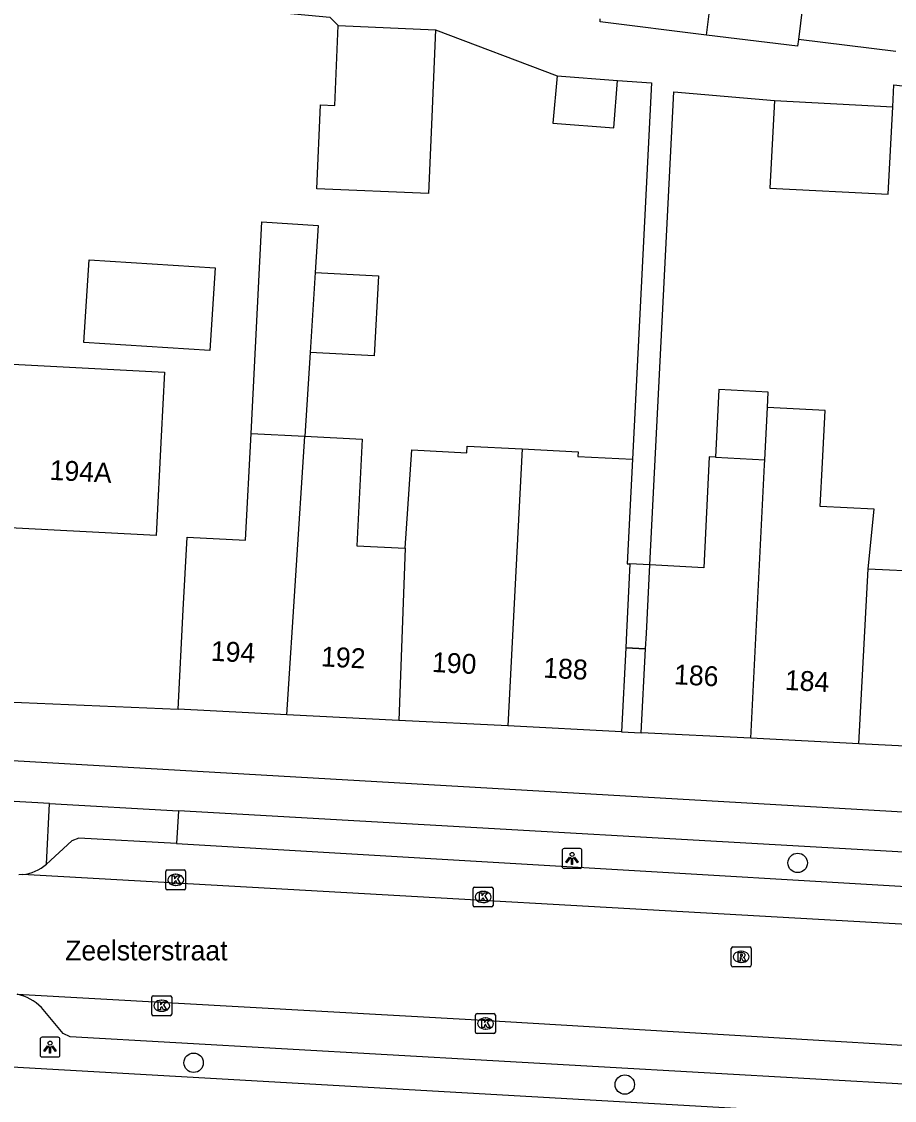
# Model space of a CAD drawing. Extents: x 158087 to 159494, y 382905 to 383981.
# Drawn here: x 158409.1 to 158453.1, y 383167.5 to 383221.8 of the extents above; entities that cross this region are included whole.
import ezdxf

# ---------------------------------------------------------------- set-up
doc = ezdxf.new("R2010")
doc.units = 0
for name, color, linetype in [('IMGEO_Boom', 7, 'Continuous'), ('IMGEO_Fietspad_gesloten', 7, 'Continuous'), ('IMGEO_Kolk', 7, 'Continuous'), ('IMGEO_Lichtpunt', 7, 'Continuous'), ('IMGEO_Openbare_ruimte_label', 7, 'Continuous'), ('IMGEO_Pand', 7, 'Continuous'), ('IMGEO_Pand_nummerreeks', 7, 'Continuous'), ('IMGEO_Pand_overbouw', 7, 'Continuous'), ('IMGEO_Parkeervlak_open', 7, 'Continuous'), ('IMGEO_Rijbaan_lokaal_gesloten', 7, 'Continuous'), ('IMGEO_Rioolput', 7, 'Continuous'), ('IMGEO_Voetpad_open', 7, 'Continuous')]:
    doc.layers.add(name, color=color, linetype=linetype)

msp = doc.modelspace()

# ---------------------------------------------------------------- linework, layer by layer
at = {"layer": 'IMGEO_Boom'}
for centre in [(158448.215, 383179.424), (158417.805, 383169.369), (158439.511, 383168.271)]:
    msp.add_circle(centre, 0.489, dxfattribs=at)
at = {"layer": 'IMGEO_Fietspad_gesloten'}
for points in [[(158375.483, 383186.486), (158469.526, 383181.066)], [(158410.542, 383182.413), (158376.349, 383184.334)], [(158410.542, 383182.413), (158417.046, 383182.047)], [(158474.658, 383178.653), (158459.444, 383179.637), (158417.046, 383182.047)], [(158375.415, 383171.065), (158464.529, 383165.969), (158487.406, 383164.364)]]:
    msp.add_lwpolyline(points, dxfattribs=at)
at = {"layer": 'IMGEO_Kolk'}
for p, q in [((158416.402, 383178.144), (158416.402, 383178.996)), ((158416.477, 383179.07), (158417.329, 383179.07)), ((158416.89, 383178.85), (158416.915, 383178.85)), ((158417.403, 383178.996), (158417.403, 383178.144)), ((158417.329, 383178.07), (158416.477, 383178.07)), ((158416.913, 383178.29), (158416.888, 383178.29)), ((158431.878, 383177.284), (158431.878, 383178.136)), ((158431.953, 383178.21), (158432.805, 383178.21)), ((158432.879, 383178.136), (158432.879, 383177.284)), ((158432.366, 383177.99), (158432.391, 383177.99)), ((158432.805, 383177.21), (158431.953, 383177.21)), ((158432.389, 383177.43), (158432.364, 383177.43)), ((158415.699, 383171.809), (158415.699, 383172.661)), ((158415.774, 383172.735), (158416.626, 383172.735)), ((158416.7, 383172.661), (158416.7, 383171.809)), ((158416.187, 383172.515), (158416.212, 383172.515)), ((158416.626, 383171.735), (158415.774, 383171.735)), ((158416.21, 383171.955), (158416.185, 383171.955)), ((158431.997, 383170.915), (158431.997, 383171.767)), ((158432.072, 383171.841), (158432.924, 383171.841)), ((158432.485, 383171.621), (158432.51, 383171.621)), ((158432.998, 383171.767), (158432.998, 383170.915)), ((158432.508, 383171.061), (158432.483, 383171.061)), ((158432.924, 383170.841), (158432.072, 383170.841))]:
    msp.add_line(p, q, dxfattribs=at)
for points in [[(158416.402, 383178.144), (158416.402, 383178.996)], [(158416.477, 383179.07), (158417.329, 383179.07)], [(158416.723, 383178.77), (158416.846, 383178.77), (158416.846, 383178.619), (158416.976, 383178.77), (158417.14, 383178.77), (158416.994, 383178.619), (158417.147, 383178.37), (158416.995, 383178.37), (158416.91, 383178.534), (158416.846, 383178.467), (158416.846, 383178.37), (158416.723, 383178.37), (158416.723, 383178.77)], [(158417.403, 383178.996), (158417.403, 383178.144)], [(158417.329, 383178.07), (158416.477, 383178.07)], [(158431.878, 383177.284), (158431.878, 383178.136)], [(158431.953, 383178.21), (158432.805, 383178.21)], [(158432.879, 383178.136), (158432.879, 383177.284)], [(158432.199, 383177.91), (158432.322, 383177.91), (158432.322, 383177.759), (158432.452, 383177.91), (158432.616, 383177.91), (158432.47, 383177.759), (158432.623, 383177.51), (158432.471, 383177.51), (158432.386, 383177.674), (158432.322, 383177.607), (158432.322, 383177.51), (158432.199, 383177.51), (158432.199, 383177.91)], [(158432.805, 383177.21), (158431.953, 383177.21)], [(158415.699, 383171.809), (158415.699, 383172.661)], [(158415.774, 383172.735), (158416.626, 383172.735)], [(158416.7, 383172.661), (158416.7, 383171.809)], [(158416.02, 383172.435), (158416.143, 383172.435), (158416.143, 383172.284), (158416.273, 383172.435), (158416.437, 383172.435), (158416.291, 383172.284), (158416.444, 383172.035), (158416.292, 383172.035), (158416.207, 383172.199), (158416.143, 383172.132), (158416.143, 383172.035), (158416.02, 383172.035), (158416.02, 383172.435)], [(158416.626, 383171.735), (158415.774, 383171.735)], [(158431.997, 383170.915), (158431.997, 383171.767)], [(158432.072, 383171.841), (158432.924, 383171.841)], [(158432.318, 383171.541), (158432.441, 383171.541), (158432.441, 383171.39), (158432.571, 383171.541), (158432.735, 383171.541), (158432.589, 383171.39), (158432.742, 383171.141), (158432.59, 383171.141), (158432.505, 383171.305), (158432.441, 383171.238), (158432.441, 383171.141), (158432.318, 383171.141), (158432.318, 383171.541)], [(158432.998, 383171.767), (158432.998, 383170.915)], [(158432.924, 383170.841), (158432.072, 383170.841)]]:
    msp.add_lwpolyline(points, dxfattribs=at)
for centre, start, end in [((158416.479, 383178.994), 91.552, 178.448), ((158416.479, 383178.994), 91.552, 178.448), ((158417.327, 383178.994), 1.552, 88.448), ((158417.327, 383178.994), 1.552, 88.448), ((158416.479, 383178.146), 181.552, 268.448), ((158416.479, 383178.146), 181.552, 268.448), ((158417.327, 383178.146), 271.552, 358.448), ((158417.327, 383178.146), 271.552, 358.448), ((158431.955, 383178.134), 91.552, 178.448), ((158431.955, 383178.134), 91.552, 178.448), ((158432.803, 383178.134), 1.552, 88.448), ((158432.803, 383178.134), 1.552, 88.448), ((158431.955, 383177.286), 181.552, 268.448), ((158431.955, 383177.286), 181.552, 268.448), ((158432.803, 383177.286), 271.552, 358.448), ((158432.803, 383177.286), 271.552, 358.448), ((158415.776, 383172.659), 91.552, 178.448), ((158415.776, 383172.659), 91.552, 178.448), ((158416.624, 383172.659), 1.552, 88.448), ((158416.624, 383172.659), 1.552, 88.448), ((158415.776, 383171.811), 181.552, 268.448), ((158415.776, 383171.811), 181.552, 268.448), ((158416.624, 383171.811), 271.552, 358.448), ((158416.624, 383171.811), 271.552, 358.448), ((158432.074, 383171.765), 91.552, 178.448), ((158432.074, 383171.765), 91.552, 178.448), ((158432.922, 383171.765), 1.552, 88.448), ((158432.922, 383171.765), 1.552, 88.448), ((158432.074, 383170.917), 181.552, 268.448), ((158432.074, 383170.917), 181.552, 268.448), ((158432.922, 383170.917), 271.552, 358.448), ((158432.922, 383170.917), 271.552, 358.448)]:
    msp.add_arc(centre, 0.0765, start, end, dxfattribs=at)
for centre, major_axis, ratio, start_param, end_param in [((158416.889, 383178.57), (-0.387, 0.002), 0.722429, 4.712389, 7.853982), ((158416.914, 383178.57), (-0.39, 0.002), 0.717154, 1.570796, 4.712389), ((158432.365, 383177.71), (-0.387, 0.002), 0.722429, 4.712389, 7.853982), ((158432.39, 383177.71), (-0.39, 0.002), 0.717154, 1.570796, 4.712389), ((158416.186, 383172.235), (-0.387, 0.002), 0.722429, 4.712389, 7.853982), ((158416.211, 383172.235), (-0.39, 0.002), 0.717154, 1.570796, 4.712389), ((158432.484, 383171.341), (-0.387, 0.002), 0.722429, 4.712389, 7.853982), ((158432.509, 383171.341), (-0.39, 0.002), 0.717154, 1.570796, 4.712389)]:
    msp.add_ellipse(centre, major_axis=major_axis, ratio=ratio, start_param=start_param, end_param=end_param, dxfattribs=at)
at = {"layer": 'IMGEO_Lichtpunt'}
for p, q in [((158436.36, 383180.052), (158436.36, 383179.245)), ((158436.36, 383180.052), (158436.36, 383179.245)), ((158437.262, 383180.147), (158436.454, 383180.147)), ((158437.262, 383180.147), (158436.454, 383180.147)), ((158437.356, 383179.245), (158437.356, 383180.052)), ((158437.356, 383179.245), (158437.356, 383180.052)), ((158436.454, 383179.151), (158437.262, 383179.151)), ((158436.454, 383179.151), (158437.262, 383179.151)), ((158410.081, 383170.559), (158410.081, 383169.752)), ((158410.081, 383170.559), (158410.081, 383169.752)), ((158410.983, 383170.654), (158410.175, 383170.654)), ((158410.983, 383170.654), (158410.175, 383170.654)), ((158411.077, 383169.752), (158411.077, 383170.559)), ((158411.077, 383169.752), (158411.077, 383170.559)), ((158410.175, 383169.658), (158410.983, 383169.658)), ((158410.175, 383169.658), (158410.983, 383169.658))]:
    msp.add_line(p, q, dxfattribs=at)
for points in [[(158436.734, 383179.716), (158436.773, 383179.688), (158436.585, 383179.426), (158436.547, 383179.453), (158436.734, 383179.716)], [(158436.836, 383179.668), (158436.883, 383179.668), (158436.883, 383179.346), (158436.836, 383179.346), (158436.836, 383179.668)], [(158436.946, 383179.688), (158436.984, 383179.715), (158437.171, 383179.453), (158437.132, 383179.425), (158436.946, 383179.688)], [(158410.455, 383170.223), (158410.494, 383170.195), (158410.306, 383169.933), (158410.268, 383169.96), (158410.455, 383170.223)], [(158410.557, 383170.175), (158410.604, 383170.175), (158410.604, 383169.853), (158410.557, 383169.853), (158410.557, 383170.175)], [(158410.667, 383170.195), (158410.705, 383170.222), (158410.892, 383169.96), (158410.853, 383169.932), (158410.667, 383170.195)]]:
    msp.add_lwpolyline(points, dxfattribs=at)
for centre in [(158436.859, 383179.85), (158410.58, 383170.357)]:
    msp.add_circle(centre, 0.0994, dxfattribs=at)
for centre, start, end in [((158436.454, 383180.052), 90, 180), ((158436.454, 383180.052), 90, 180), ((158437.262, 383180.052), 0, 90), ((158437.262, 383180.052), 0, 90), ((158436.454, 383179.245), 180, 270), ((158436.454, 383179.245), 180, 270), ((158437.262, 383179.245), 270, 0), ((158437.262, 383179.245), 270, 360), ((158410.175, 383170.559), 90, 180), ((158410.175, 383170.559), 90, 180), ((158410.983, 383170.559), 0, 90), ((158410.983, 383170.559), 0, 90), ((158410.175, 383169.752), 180, 270), ((158410.175, 383169.752), 180, 270), ((158410.983, 383169.752), 270, 0), ((158410.983, 383169.752), 270, 360)]:
    msp.add_arc(centre, 0.0946, start, end, dxfattribs=at)
at = {"layer": 'IMGEO_Pand'}
for points in [[(158443.627, 383221.079), (158444.058, 383224.585), (158448.643, 383224.022)], [(158448.643, 383224.022), (158448.254, 383220.849)], [(158429.982, 383221.345), (158429.796, 383216.965), (158429.631, 383213.107), (158424.008, 383213.346), (158424.188, 383217.574), (158424.911, 383217.543), (158425.082, 383221.554)], [(158425.082, 383221.554), (158429.982, 383221.345)], [(158448.254, 383220.849), (158448.213, 383220.516), (158443.627, 383221.079)], [(158453.163, 383220.247), (158448.254, 383220.849)], [(158436.103, 383219.029), (158435.887, 383216.645), (158438.967, 383216.412), (158439.147, 383218.799)], [(158436.103, 383219.029), (158439.147, 383218.799)], [(158447.044, 383217.782), (158446.812, 383213.381), (158452.775, 383213.066), (158453.008, 383217.467)], [(158447.044, 383217.782), (158453.008, 383217.467)], [(158420.694, 383201.031), (158421.236, 383211.685), (158424.075, 383211.503), (158423.923, 383209.131)], [(158418.622, 383205.199), (158412.275, 383205.605), (158412.541, 383209.772), (158418.888, 383209.367), (158418.622, 383205.199)], [(158423.923, 383209.131), (158427.106, 383208.97), (158426.902, 383204.938), (158423.666, 383205.102)], [(158423.923, 383209.131), (158423.666, 383205.102)], [(158423.666, 383205.102), (158423.397, 383200.894)], [(158407.719, 383204.562), (158416.336, 383204.124), (158416.172, 383200.899), (158415.919, 383195.905), (158407.244, 383196.345)], [(158451.764, 383194.228), (158454.628, 383194.083), (158454.761, 383196.714), (158453.63, 383196.771), (158454.022, 383204.489), (158457.922, 383204.291)], [(158446.698, 383202.334), (158446.737, 383203.114), (158444.243, 383203.24), (158444.071, 383199.836)], [(158446.562, 383199.71), (158446.698, 383202.334)], [(158451.764, 383194.228), (158452.065, 383197.217), (158449.353, 383197.354), (158449.465, 383199.563), (158449.598, 383202.186), (158446.698, 383202.334)], [(158417.034, 383187.157), (158417.287, 383192.151), (158417.473, 383195.811), (158420.421, 383195.662), (158420.694, 383201.031)], [(158420.694, 383201.031), (158423.397, 383200.894)], [(158422.502, 383186.88), (158423.397, 383200.894)], [(158423.397, 383200.894), (158426.295, 383200.747), (158426.023, 383195.378), (158428.453, 383195.254)], [(158428.453, 383195.254), (158428.783, 383200.202), (158431.564, 383200.06), (158431.581, 383200.399), (158434.349, 383200.259)], [(158434.349, 383200.259), (158433.629, 383186.315)], [(158434.349, 383200.259), (158437.166, 383200.116), (158437.153, 383199.874), (158439.902, 383199.735)], [(158439.902, 383199.735), (158439.635, 383194.473), (158439.773, 383194.466), (158439.598, 383191.019), (158439.559, 383190.246), (158439.344, 383186.025)], [(158444.071, 383199.836), (158443.765, 383199.852), (158443.482, 383194.278), (158440.772, 383194.415)], [(158444.071, 383199.836), (158446.562, 383199.71)], [(158445.855, 383185.695), (158446.549, 383199.461), (158446.562, 383199.71)], [(158428.453, 383195.254), (158428.138, 383186.594)], [(158440.343, 383185.975), (158440.558, 383190.195), (158440.597, 383190.969), (158440.772, 383194.415)], [(158451.295, 383185.419), (158451.764, 383194.228)], [(158422.502, 383186.88), (158417.034, 383187.157)], [(158428.138, 383186.594), (158422.502, 383186.88)], [(158433.629, 383186.315), (158428.138, 383186.594)], [(158439.344, 383186.025), (158433.629, 383186.315)], [(158445.855, 383185.695), (158440.343, 383185.975)], [(158451.295, 383185.419), (158445.855, 383185.695)], [(158456.951, 383185.132), (158451.295, 383185.419)]]:
    msp.add_lwpolyline(points, dxfattribs=at)
at = {"layer": 'IMGEO_Pand_overbouw'}
for points in [[(158439.559, 383190.246), (158440.558, 383190.195), (158440.597, 383190.969), (158440.772, 383194.415), (158439.773, 383194.466), (158439.598, 383191.019)], [(158440.558, 383190.195), (158439.559, 383190.246), (158439.344, 383186.025), (158440.343, 383185.975)]]:
    msp.add_lwpolyline(points, close=True, dxfattribs=at)
at = {"layer": 'IMGEO_Parkeervlak_open'}
for points in [[(158416.944, 383180.404), (158475.029, 383176.971)], [(158487.539, 383166.035), (158474.588, 383166.996), (158454.152, 383168.258), (158411.587, 383170.678), (158411.239, 383170.841), (158410.146, 383172.145)]]:
    msp.add_lwpolyline(points, dxfattribs=at)
for centre, radius, start, end in [((158409.041, 383180.845), 2.007, 274.1051, 312.4063), ((158408.332, 383170.292), 2.593, 45.5973, 76.9993)]:
    msp.add_arc(centre, radius, start, end, dxfattribs=at)
at = {"layer": 'IMGEO_Rijbaan_lokaal_gesloten'}
for points in [[(158409.185, 383178.843), (158409, 383178.829)], [(158471.933, 383175.202), (158459.655, 383175.987), (158409.185, 383178.843)], [(158408.915, 383172.819), (158432.081, 383171.528), (158470.425, 383169.248)]]:
    msp.add_lwpolyline(points, dxfattribs=at)
at = {"layer": 'IMGEO_Rioolput'}
for p, q in [((158444.871, 383174.271), (158444.871, 383175.123)), ((158444.946, 383175.197), (158445.798, 383175.197)), ((158445.359, 383174.977), (158445.384, 383174.977)), ((158445.872, 383175.123), (158445.872, 383174.271)), ((158445.382, 383174.417), (158445.357, 383174.417)), ((158445.798, 383174.197), (158444.946, 383174.197))]:
    msp.add_line(p, q, dxfattribs=at)
for points in [[(158444.871, 383174.271), (158444.871, 383175.123)], [(158444.946, 383175.197), (158445.798, 383175.197)], [(158445.46, 383174.895), (158445.208, 383174.897), (158445.208, 383174.497)], [(158445.386, 383174.816), (158445.332, 383174.816), (158445.332, 383174.735)], [(158445.872, 383175.123), (158445.872, 383174.271)], [(158445.208, 383174.497), (158445.332, 383174.497), (158445.332, 383174.659), (158445.343, 383174.659)], [(158445.332, 383174.735), (158445.384, 383174.735)], [(158445.39, 383174.63), (158445.461, 383174.497), (158445.601, 383174.497), (158445.536, 383174.623)], [(158445.798, 383174.197), (158444.946, 383174.197)]]:
    msp.add_lwpolyline(points, dxfattribs=at)
for centre, radius, start, end in [((158444.948, 383175.121), 0.0765, 91.552, 178.448), ((158444.948, 383175.121), 0.0765, 91.552, 178.448), ((158445.392, 383174.72), 0.0964, 77.0061, 93.1865), ((158445.406, 383174.777), 0.0378, 276.6634, 79.6772), ((158445.459, 383174.785), 0.109, 350.3612, 89.416), ((158445.457, 383174.785), 0.112, 277.5842, 350.9817), ((158445.796, 383175.121), 0.0765, 1.552, 88.448), ((158445.796, 383175.121), 0.0765, 1.552, 88.448), ((158444.948, 383174.273), 0.0765, 181.552, 268.448), ((158444.948, 383174.273), 0.0765, 181.552, 268.448), ((158445.342, 383174.606), 0.0533, 26.0293, 88.6989), ((158445.368, 383174.924), 0.19, 274.7715, 282.9687), ((158445.441, 383174.57), 0.108, 29.5134, 73.7905), ((158445.796, 383174.273), 0.0765, 271.552, 358.448), ((158445.796, 383174.273), 0.0765, 271.552, 358.448)]:
    msp.add_arc(centre, radius, start, end, dxfattribs=at)
for centre, major_axis, ratio, start_param, end_param in [((158445.358, 383174.697), (-0.387, 0.002), 0.722429, 4.712389, 7.853982), ((158445.383, 383174.697), (-0.39, 0.002), 0.717154, 1.570796, 4.712389)]:
    msp.add_ellipse(centre, major_axis=major_axis, ratio=ratio, start_param=start_param, end_param=end_param, dxfattribs=at)
at = {"layer": 'IMGEO_Voetpad_open'}
for points in [[(158385.005, 383225.706), (158424.655, 383221.973), (158425.082, 383221.554)], [(158443.627, 383221.079), (158438.265, 383221.743), (158438.279, 383221.903)], [(158429.982, 383221.345), (158436.103, 383219.029)], [(158439.147, 383218.799), (158440.862, 383218.669), (158439.902, 383199.735)], [(158440.772, 383194.415), (158441.976, 383218.227), (158447.044, 383217.782)], [(158453.008, 383217.467), (158453.059, 383218.568), (158472.459, 383216.343), (158476.743, 383215.82)], [(158400.444, 383187.871), (158417.034, 383187.157)], [(158439.344, 383186.025), (158440.343, 383185.975)], [(158410.395, 383179.363), (158410.542, 383182.413)], [(158417.046, 383182.047), (158416.944, 383180.404)], [(158416.944, 383180.404), (158412.029, 383180.672), (158411.674, 383180.537), (158410.395, 383179.363)]]:
    msp.add_lwpolyline(points, dxfattribs=at)

# ---------------------------------------------------------------- texts
at = {"layer": 'IMGEO_Openbare_ruimte_label'}
msp.add_text('Zeelsterstraat', height=1, rotation=360, dxfattribs=at).set_placement((158411.337, 383174.518))
at = {"layer": 'IMGEO_Pand_nummerreeks'}
for s, rotation, p in [('194A', 357.0958, (158410.541, 383198.702)), ('194', 357.0974, (158418.652, 383189.599)), ('192', 357.0975, (158424.202, 383189.317)), ('190', 357.0932, (158429.786, 383189.034)), ('188', 357.0951, (158435.389, 383188.75)), ('186', 357.0951, (158441.975, 383188.416)), ('184', 357.0951, (158447.555, 383188.132))]:
    msp.add_text(s, height=1, rotation=rotation, dxfattribs=at).set_placement(p)

doc.saveas('drawing.dxf')
